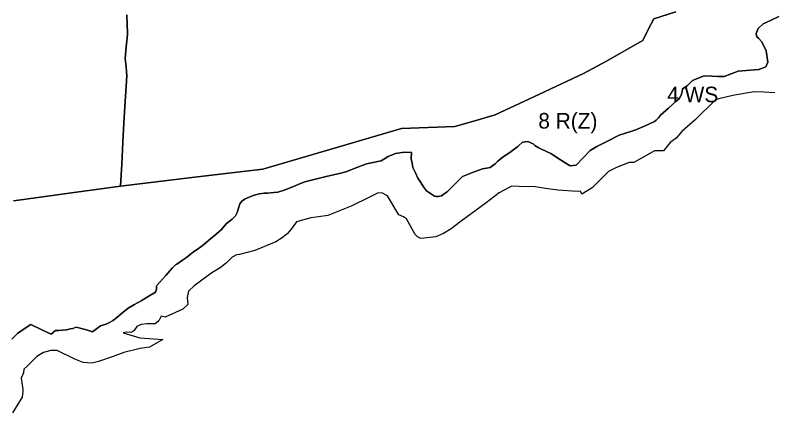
# Model space of a CAD drawing. Extents: x -294445 to -292055, y 21869 to 23693.
# Drawn here: x -293269.7 to -292783, y 21985.3 to 22240.3 of the extents above; entities that cross this region are included whole.
import ezdxf

# ---------------------------------------------------------------- set-up
doc = ezdxf.new("R2010")
doc.units = 0
doc.layers.add('linie_rozgraniczajace', color=7, linetype='Continuous')
doc.layers.add('oznaczenia_przeznaczen', color=7, linetype='Continuous')

msp = doc.modelspace()

# ---------------------------------------------------------------- linework, layer by layer
at = {"layer": 'linie_rozgraniczajace'}
for points in [[(-293270.775, 22121.14), (-293267.58, 22121.58), (-293250.55, 22123.92), (-293233.52, 22126.26), (-293217.836, 22128.485), (-293202.153, 22130.71), (-293156.624, 22136.12), (-293111.096, 22141.53), (-293066.647, 22154.537), (-293022.15, 22167.55), (-293005.125, 22168.175), (-292988.1, 22168.8), (-292975.1, 22172.62), (-292962.1, 22176.44), (-292933.815, 22189.69), (-292905.53, 22202.94), (-292890.95, 22210.72), (-292879.29, 22217.385), (-292867.63, 22224.05), (-292864.09, 22231.025), (-292860.55, 22238), (-292846.352, 22242.462)], [(-292846.352, 22242.462), (-292860.55, 22238), (-292864.09, 22231.025), (-292867.63, 22224.05), (-292879.29, 22217.385), (-292890.95, 22210.72), (-292905.53, 22202.94), (-292933.815, 22189.69), (-292962.1, 22176.44), (-292975.1, 22172.62), (-292988.1, 22168.8), (-293005.125, 22168.175), (-293022.15, 22167.55), (-293066.647, 22154.537), (-293111.096, 22141.53), (-293156.624, 22136.12), (-293202.153, 22130.71), (-293201.456, 22144.805), (-293200.76, 22158.9), (-293200.33, 22166.94), (-293199.9, 22174.98), (-293199.015, 22188.22), (-293198.13, 22201.46), (-293198.69, 22206.99), (-293199.25, 22212.52), (-293198.545, 22220.1), (-293197.84, 22227.68), (-293197.64, 22228.82), (-293197.93, 22234.635), (-293198.22, 22240.45)], [(-293198.22, 22240.45), (-293197.93, 22234.635), (-293197.64, 22228.82), (-293197.84, 22227.68), (-293198.545, 22220.1), (-293199.25, 22212.52), (-293198.69, 22206.99), (-293198.13, 22201.46), (-293199.015, 22188.22), (-293199.9, 22174.98), (-293200.33, 22166.94), (-293200.76, 22158.9), (-293201.456, 22144.805), (-293202.153, 22130.71), (-293217.836, 22128.485), (-293233.52, 22126.26), (-293250.55, 22123.92), (-293267.58, 22121.58), (-293270.775, 22121.14)], [(-293070.38, 22136.8), (-293065.67, 22137.855), (-293060.96, 22138.91), (-293057.31, 22140.1), (-293052.515, 22141.95), (-293044.53, 22145), (-293035.12, 22146.84), (-293030.7, 22149.57), (-293026.116, 22151.628), (-293020.195, 22152.344), (-293015.81, 22152.17), (-293015.91, 22148.19), (-293015.39, 22145.36), (-293014.87, 22142.53), (-293013.315, 22139.15), (-293011.76, 22135.77), (-293009.895, 22132.935), (-293008.03, 22130.1), (-293006.11, 22127.69), (-293003.625, 22125.915), (-293001.14, 22124.14), (-292999.925, 22124.105), (-292998.71, 22124.07), (-292997.68, 22124.295), (-292996.65, 22124.52), (-292994.825, 22125.76), (-292993, 22127), (-292988.005, 22131.935), (-292983.01, 22136.87), (-292976.625, 22139.35), (-292970.24, 22141.83), (-292967.825, 22142.245), (-292965.41, 22142.66), (-292962.26, 22144.96), (-292960.58, 22146.44), (-292958.9, 22147.92), (-292956.46, 22149.94), (-292952.78, 22152.28), (-292950.225, 22154.15), (-292947.67, 22156.02), (-292947.219, 22156.449), (-292944.77, 22158.78), (-292941.31, 22159.34), (-292937.92, 22157.71), (-292936.79, 22156.61), (-292934.63, 22155.38), (-292932.925, 22154.59), (-292928.905, 22152.69), (-292926.59, 22151.58), (-292920.35, 22147.52), (-292917.275, 22145.64), (-292914.2, 22143.76), (-292910.28, 22144.11), (-292905.845, 22148.8), (-292901.41, 22153.49), (-292896.94, 22155.99), (-292889.805, 22159.685), (-292882.67, 22163.38), (-292878.6, 22164.67), (-292874.53, 22165.96), (-292871.961, 22166.677), (-292866.03, 22169.41), (-292860.04, 22172.17), (-292858.943, 22172.999), (-292857.525, 22174.56), (-292856.15, 22176.08), (-292851.14, 22180.615), (-292846.13, 22185.15), (-292844.29, 22186.63), (-292843.495, 22188.16), (-292842.7, 22189.69), (-292842.42, 22191.42), (-292842.14, 22193.15), (-292840.5, 22194.22), (-292838.86, 22195.29), (-292837.275, 22196.885), (-292835.69, 22198.48), (-292832.2, 22199.91), (-292828.27, 22201.4), (-292823.41, 22201.08), (-292819.41, 22201.01), (-292815.41, 22200.94), (-292810.935, 22202.64), (-292806.46, 22204.34), (-292796.13, 22205.35), (-292793.29, 22205.42), (-292788.71, 22207.13), (-292787.52, 22210.13), (-292788.61, 22217.41), (-292789.6, 22219.83), (-292791.6, 22223.46), (-292793.15, 22225.31), (-292794.53, 22226.36), (-292794.97, 22228.6), (-292793.78, 22231.73), (-292790.56, 22234.78), (-292785.73, 22236.93), (-292780.355, 22239.515)], [(-292780.355, 22239.515), (-292785.73, 22236.93), (-292790.56, 22234.78), (-292793.78, 22231.73), (-292794.97, 22228.6), (-292794.53, 22226.36), (-292793.15, 22225.31), (-292791.6, 22223.46), (-292789.6, 22219.83), (-292788.61, 22217.41), (-292787.52, 22210.13), (-292788.71, 22207.13), (-292793.29, 22205.42), (-292796.13, 22205.35), (-292806.46, 22204.34), (-292810.935, 22202.64), (-292815.41, 22200.94), (-292819.41, 22201.01), (-292823.41, 22201.08), (-292828.27, 22201.4), (-292832.2, 22199.91), (-292835.69, 22198.48), (-292837.275, 22196.885), (-292838.86, 22195.29), (-292840.5, 22194.22), (-292842.14, 22193.15), (-292842.42, 22191.42), (-292842.7, 22189.69), (-292843.495, 22188.16)], [(-292843.495, 22188.16), (-292844.29, 22186.63), (-292846.13, 22185.15), (-292851.14, 22180.615), (-292856.15, 22176.08), (-292857.525, 22174.56), (-292858.943, 22172.999), (-292860.04, 22172.17), (-292866.03, 22169.41), (-292871.961, 22166.677), (-292874.53, 22165.96), (-292878.6, 22164.67), (-292882.67, 22163.38), (-292889.805, 22159.685), (-292896.94, 22155.99), (-292901.41, 22153.49), (-292905.845, 22148.8), (-292910.28, 22144.11), (-292914.2, 22143.76), (-292917.275, 22145.64), (-292920.35, 22147.52), (-292926.59, 22151.58), (-292928.905, 22152.69), (-292932.925, 22154.59), (-292934.63, 22155.38), (-292936.79, 22156.61), (-292937.92, 22157.71), (-292941.31, 22159.34), (-292944.77, 22158.78), (-292947.219, 22156.449), (-292947.67, 22156.02), (-292950.225, 22154.15), (-292952.78, 22152.28), (-292956.46, 22149.94), (-292958.9, 22147.92), (-292960.58, 22146.44), (-292962.26, 22144.96), (-292965.41, 22142.66), (-292967.825, 22142.245), (-292970.24, 22141.83), (-292976.625, 22139.35), (-292983.01, 22136.87), (-292988.005, 22131.935), (-292993, 22127), (-292994.825, 22125.76), (-292996.65, 22124.52), (-292997.68, 22124.295), (-292998.71, 22124.07), (-292999.925, 22124.105), (-293001.14, 22124.14), (-293003.625, 22125.915), (-293006.11, 22127.69), (-293008.03, 22130.1), (-293009.895, 22132.935), (-293011.76, 22135.77), (-293013.315, 22139.15), (-293014.87, 22142.53), (-293015.39, 22145.36), (-293015.91, 22148.19), (-293015.81, 22152.17), (-293020.195, 22152.344), (-293026.116, 22151.628), (-293030.7, 22149.57), (-293035.12, 22146.84), (-293044.53, 22145), (-293052.515, 22141.95), (-293057.31, 22140.1), (-293060.96, 22138.91), (-293065.67, 22137.855), (-293070.38, 22136.8), (-293076.35, 22135.335), (-293082.32, 22133.87), (-293084.13, 22133.315), (-293085.94, 22132.76), (-293088.355, 22131.74), (-293091.444, 22130.454), (-293097.42, 22128.1), (-293101.36, 22126.71), (-293104.05, 22126.54), (-293107.98, 22126.25), (-293110.1, 22126.11), (-293113.3, 22125.7), (-293117.17, 22124.71), (-293119.735, 22123.575), (-293122.3, 22122.44), (-293124.45, 22121.09), (-293125.69, 22119.36), (-293126.61, 22116.58), (-293127.53, 22113.8), (-293128.63, 22111.51), (-293130.61, 22109.4), (-293134.48, 22106.47), (-293137.51, 22102.89), (-293141.005, 22099.83), (-293144.5, 22096.77), (-293148.85, 22093.32), (-293150.74, 22091.7), (-293153.08, 22090.075), (-293155.42, 22088.45), (-293157.627, 22086.765)], [(-292782.91, 22190.48), (-292790.11, 22190.93), (-292796.21, 22191.15), (-292800, 22190.52), (-292809.85, 22188.89), (-292818.91, 22186.75), (-292820.93, 22186.03), (-292833.94, 22173.2), (-292842.64, 22165.77), (-292846.23, 22161.4), (-292850.07, 22158.72), (-292854.33, 22153.4), (-292860.15, 22153.2), (-292873.38, 22145.8), (-292876.24, 22145.91), (-292884.39, 22142.67), (-292889.63, 22140.08), (-292899.98, 22129.64), (-292906.72, 22125.54)], [(-293271.88, 22032.42), (-293268.31, 22036.13), (-293264, 22039.035), (-293259.69, 22041.94), (-293252.528, 22038.545), (-293246.59, 22035.73), (-293243.89, 22038.09), (-293241.765, 22038.115), (-293239.383, 22038.182), (-293236.916, 22038.587), (-293235.98, 22038.74), (-293234.35, 22039.09), (-293232.72, 22039.44), (-293231.635, 22039.775), (-293230.55, 22040.11), (-293224.07, 22038.54), (-293220.07, 22037.2), (-293214.95, 22041.09), (-293212.945, 22041.7), (-293210.94, 22042.31), (-293208.94, 22043.35), (-293207.365, 22044.365), (-293205.79, 22045.38), (-293200.74, 22049.57), (-293197.35, 22052.29), (-293193.205, 22054.64), (-293189.06, 22056.99), (-293184.43, 22059.84), (-293179.8, 22062.69), (-293179.06, 22064.5), (-293179.236, 22066.662), (-293173.179, 22073.433), (-293169.085, 22078.009), (-293167.081, 22080.239), (-293166.18, 22080.68), (-293163.075, 22082.82), (-293160.011, 22084.945), (-293157.627, 22086.765), (-293155.42, 22088.45), (-293153.08, 22090.075), (-293150.74, 22091.7), (-293148.85, 22093.32), (-293144.5, 22096.77), (-293141.005, 22099.83), (-293137.51, 22102.89), (-293134.48, 22106.47), (-293130.61, 22109.4), (-293128.63, 22111.51), (-293127.53, 22113.8), (-293126.61, 22116.58), (-293125.69, 22119.36), (-293124.45, 22121.09), (-293122.3, 22122.44), (-293119.735, 22123.575), (-293117.17, 22124.71), (-293113.3, 22125.7), (-293110.1, 22126.11), (-293107.98, 22126.25), (-293104.05, 22126.54), (-293101.36, 22126.71), (-293097.42, 22128.1), (-293091.444, 22130.454), (-293088.355, 22131.74), (-293085.94, 22132.76), (-293084.13, 22133.315), (-293082.32, 22133.87), (-293076.35, 22135.335), (-293070.38, 22136.8)], [(-292906.72, 22125.54), (-292907.6, 22127.39), (-292909.38, 22127.21), (-292922.1, 22128.16), (-292929.89, 22129.1), (-292936.46, 22130.21), (-292946.74, 22130.5), (-292951.48, 22130.64), (-292953.73, 22129.65), (-292959.62, 22126.27), (-292968.02, 22119.9), (-292984.01, 22108.21), (-292990.31, 22103.3), (-292995.22, 22100.18), (-293000.26, 22098.15), (-293009.8, 22096.98), (-293011.98, 22098.14), (-293013.36, 22099.65), (-293018.95, 22109.69), (-293020.89, 22110.99), (-293023.93, 22112.32), (-293031.22, 22124.43), (-293034.42, 22126.17), (-293037.05, 22126.29), (-293042.68, 22123.56), (-293054.52, 22117.73), (-293069.41, 22111.82), (-293076.94, 22110.84), (-293080.23, 22110.24), (-293089.56, 22107.83), (-293092.86, 22102.96), (-293095.35, 22100.03), (-293098.65, 22097.51), (-293102.74, 22094.86), (-293116.21, 22089.39), (-293125.98, 22086.79), (-293127.88, 22086.54), (-293130.79, 22085.12), (-293134.42, 22081.37), (-293138.29, 22078.21), (-293143.8, 22075.09), (-293155.13, 22066.81), (-293158.57, 22063.21), (-293159.41, 22059.2), (-293159.02, 22054.69), (-293162.26, 22051.69), (-293173.57, 22046.67), (-293176.2, 22047.25), (-293177.63, 22044.16), (-293180.07, 22042.42), (-293185.28, 22042.33), (-293189.08, 22041.88), (-293191.7, 22040.71), (-293193.77, 22037.92), (-293195.59, 22036.75), (-293198.5, 22036.89), (-293200.57, 22036.67), (-293189.82, 22033.27), (-293175.12, 22032.31), (-293183.55, 22027.33), (-293189.57, 22026.43), (-293200.17, 22024.01), (-293207.47, 22021.1), (-293216.36, 22018.14), (-293220.68, 22017.18), (-293226.11, 22017.64), (-293231.45, 22019.65), (-293242.85, 22025.18), (-293246.95, 22025.19), (-293251.46, 22024.02), (-293255.93, 22021.4), (-293262.33, 22015.01), (-293264.16, 22013.25), (-293264.44, 22010.96), (-293265.93, 22007.52), (-293265.26, 22003.26), (-293264.9, 22000), (-293264.8, 21999.1), (-293265.33, 21995.34), (-293271.48, 21985.26)], [(-293157.627, 22086.765), (-293160.011, 22084.945), (-293163.075, 22082.82), (-293166.18, 22080.68), (-293167.081, 22080.239), (-293169.085, 22078.009), (-293173.179, 22073.433), (-293179.236, 22066.662), (-293179.06, 22064.5), (-293179.8, 22062.69), (-293184.43, 22059.84), (-293189.06, 22056.99), (-293193.205, 22054.64), (-293197.35, 22052.29), (-293200.74, 22049.57), (-293205.79, 22045.38), (-293207.365, 22044.365), (-293208.94, 22043.35), (-293210.94, 22042.31), (-293212.945, 22041.7), (-293214.95, 22041.09), (-293220.07, 22037.2), (-293224.07, 22038.54), (-293230.55, 22040.11), (-293231.635, 22039.775), (-293232.72, 22039.44), (-293234.35, 22039.09), (-293235.98, 22038.74), (-293236.916, 22038.587), (-293239.383, 22038.182), (-293241.765, 22038.115), (-293243.89, 22038.09), (-293246.59, 22035.73), (-293252.528, 22038.545), (-293259.69, 22041.94), (-293264, 22039.035), (-293268.31, 22036.13), (-293271.88, 22032.42)]]:
    msp.add_lwpolyline(points, dxfattribs=at)

# ---------------------------------------------------------------- texts
at = {"layer": 'oznaczenia_przeznaczen'}
for s, p in [('4 WS', (-292851.941, 22184.431)), ('8 R(Z)', (-292934.543, 22167.577))]:
    msp.add_text(s, height=10, dxfattribs=at).set_placement(p)

doc.saveas('drawing.dxf')
